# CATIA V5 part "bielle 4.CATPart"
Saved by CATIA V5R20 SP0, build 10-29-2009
Part number: Pièce1
Bounding box of the stored display mesh (mm): x 0 to 35, y -76.416 to 103.584, z 30.028 to 49.972
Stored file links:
  E:\EDELI\wjacquemont\Edeli_2012_122_wjacquemont\bielle 4.CATPart
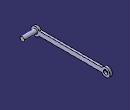
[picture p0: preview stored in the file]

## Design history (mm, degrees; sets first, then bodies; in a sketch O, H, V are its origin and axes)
Parameters
  `Longueur bièle` = 160 mm
Body1 (main body)
  Sketch1 on yz-plane, origin (0, 0, 0), H (0, 1, 0), V (0, 0, 1)
    line L1 (-57.7553, 45) -> (84.9242, 45)
    line L2 (-57.7553, 35) -> (84.9242, 35)
    axis line L3 (-76.4155, 40) -> (33.5845, 40)
    point P5 (-76.4155, 40)
    arc A1 centre (-66.4155, 40) radius 10 from (-57.7553, 45) to (-57.7553, 35) ccw
    point P7 (-66.4155, 40)
    arc A2 centre (93.5845, 40) radius 10 from (84.9242, 35) to (84.9242, 45) ccw
    point P8 (93.5845, 40)
    circle A3 centre (93.5845, 40) radius 5
    circle A4 centre (-66.4155, 40) radius 5
    distance L2 L1 = 10
    radius A1 = 10
    radius A2 = 10
    distance P8 P7 = 160 {= `Longueur bièle`}
    radius A3 = 5
    radius A4 = 5
    horizontal: L1 H, L2 H, L3 H
    coincidence: A1 P5, P7 L3, P8 L3
    symmetry: L2 L1 L3
  Pad1: profile Sketch1, direction (1, 0, 0), length 5
  Sketch2 on start face of Pad1, origin (0, 0, 0), H (0, -1, 0), V (0, 0, 1)
    circle A1 centre (66.4155, 40) radius 5
    reference projected circle E1 centre (66.4155, 40) radius 5 from edge [face of Pad1 from Sketch1.A4 | start face of Pad1]
    coincidence: A1 E1
  Pad2: profile Sketch2, direction (1, 0, 0), length 35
